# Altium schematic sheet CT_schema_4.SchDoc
size 296 x 173 mm
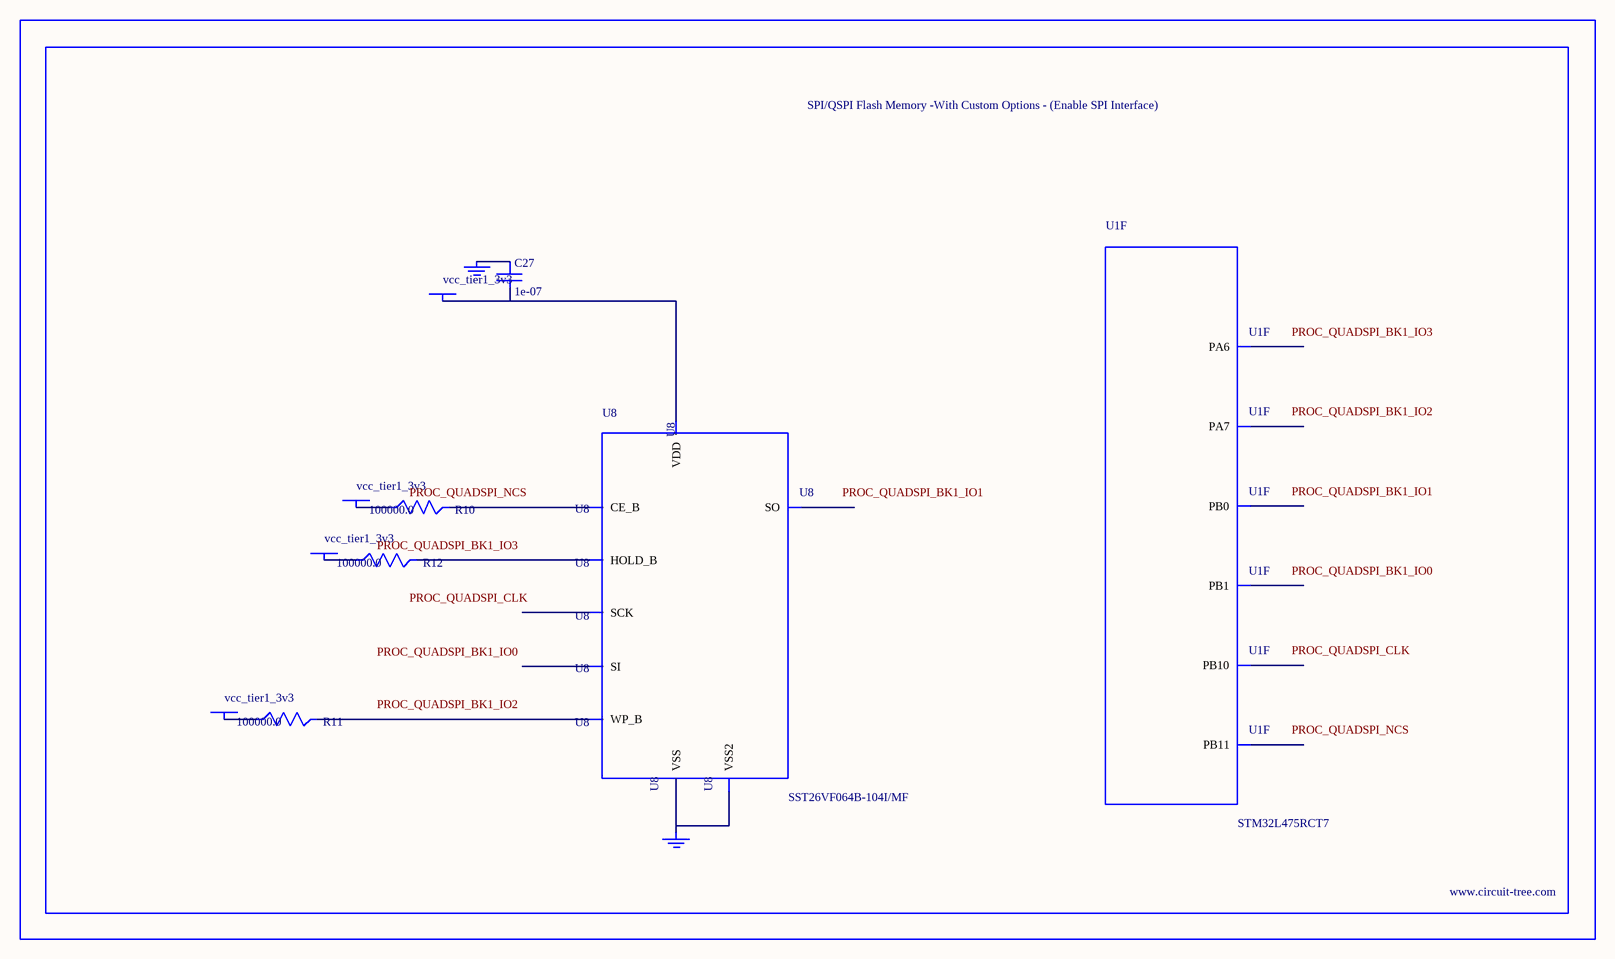
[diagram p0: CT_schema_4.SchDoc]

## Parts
BORDER3  (no value)
C27  1e-07  [C0402]
GND_INSTANCE_3_0  (no value)
GND_INSTANCE_3_1  (no value)
POWER_INSTANCE_3_0  vcc_tier1_3v3
POWER_INSTANCE_3_1  vcc_tier1_3v3
POWER_INSTANCE_3_2  vcc_tier1_3v3
POWER_INSTANCE_3_3  vcc_tier1_3v3
R10  100000.0  [R0603]
R11  100000.0  [R0603]
R12  100000.0  [R0603]
U1  STM32L475RCT7  [LQFP64]  (part F of 8)
U8  SST26VF064B-104I/MF  [WFDN-8]

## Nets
NetC27_1: C27.1 GND_INSTANCE_3_0.0(GND)
NetC27_2: C27.2 POWER_INSTANCE_3_3.0(PWR) U8.8(VDD)
NetGND_INSTANCE_3_1_0: GND_INSTANCE_3_1.0(GND) U8.4(VSS) U8.9(VSS2)
NetPOWER_INSTANCE_3_0_0: POWER_INSTANCE_3_0.0(PWR) R10.1
NetPOWER_INSTANCE_3_1_0: POWER_INSTANCE_3_1.0(PWR) R11.1
NetPOWER_INSTANCE_3_2_0: POWER_INSTANCE_3_2.0(PWR) R12.1
NetR10_2: R10.2 U8.1(CE_B)
NetR11_2: R11.2 U8.3(WP_B)
NetR12_2: R12.2 U8.7(HOLD_B)

Not connected (* = marked no-connect by the designer): U1 22(PA6) 23(PA7) 26(PB0) 27(PB1) 29(PB10) 30(PB11); U8 2(SO) 5(SI) 6(SCK)

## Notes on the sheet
- Labels drawn without touching a wire or pin: PROC_QUADSPI_BK1_IO0, PROC_QUADSPI_BK1_IO1, PROC_QUADSPI_BK1_IO2, PROC_QUADSPI_BK1_IO3, PROC_QUADSPI_CLK, PROC_QUADSPI_NCS

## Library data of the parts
BORDER3 = BORDER_PAGE3
C27 = C0402C104K3RACTU
GND_INSTANCE_3_0 GND_INSTANCE_3_1 = GND
POWER_INSTANCE_3_0-POWER_INSTANCE_3_3 = PWR
R10-R12 = RC0603JR-07100KL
